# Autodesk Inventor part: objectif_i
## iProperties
Created: 2011-01
Part Number: objectif_i
Document SubType Name: Modeling
Designer: eric
Density: 1 g/cm^3
Mass: 20.8474 g
Surface Area: 221.533 cm^2
Volume: 20.8474 cm^3
Author: eric
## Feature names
1. Extrusion1
2. Extrusion2
3. Congé1 [Fillet]
4. Réseau circulaire1 [Circular Pattern]
5. Extrusion3
6. Extrusion4
7. Extrusion5
8. Hélicoïde1
